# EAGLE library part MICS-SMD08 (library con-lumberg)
CONNECTOR
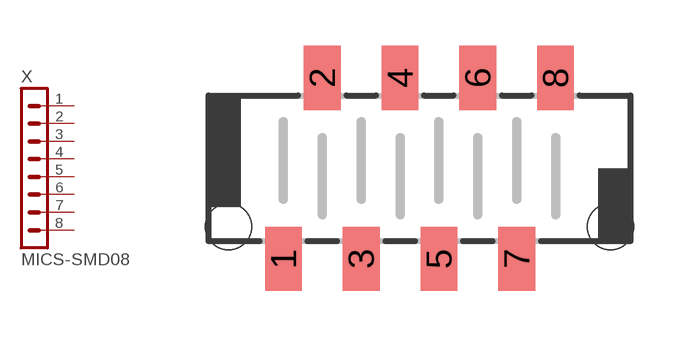
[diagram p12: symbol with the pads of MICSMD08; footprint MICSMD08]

Designator prefix X

## MICS-SMD08 (OC_FARNELL: unknown; OC_NEWARK: unknown)  [MICSMD08]
1  1  pas
2  2  pas
3  3  pas
4  4  pas
5  5  pas
6  6  pas
7  7  pas
8  8  pas

## Footprint MICSMD08 (pad centres in mm)
CONNECTOR
smd 1.2 x 2.1: 1 -4.445,-2.959; 2 -3.175,2.959; 3 -1.905,-2.959; 4 -0.635,2.959; 5 0.635,-2.959; 6 1.905,2.959; 7 3.175,-2.959; 8 4.445,2.959
hole 1.5 at 6.245,-1.912
hole 1.5 at -6.245,-1.912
